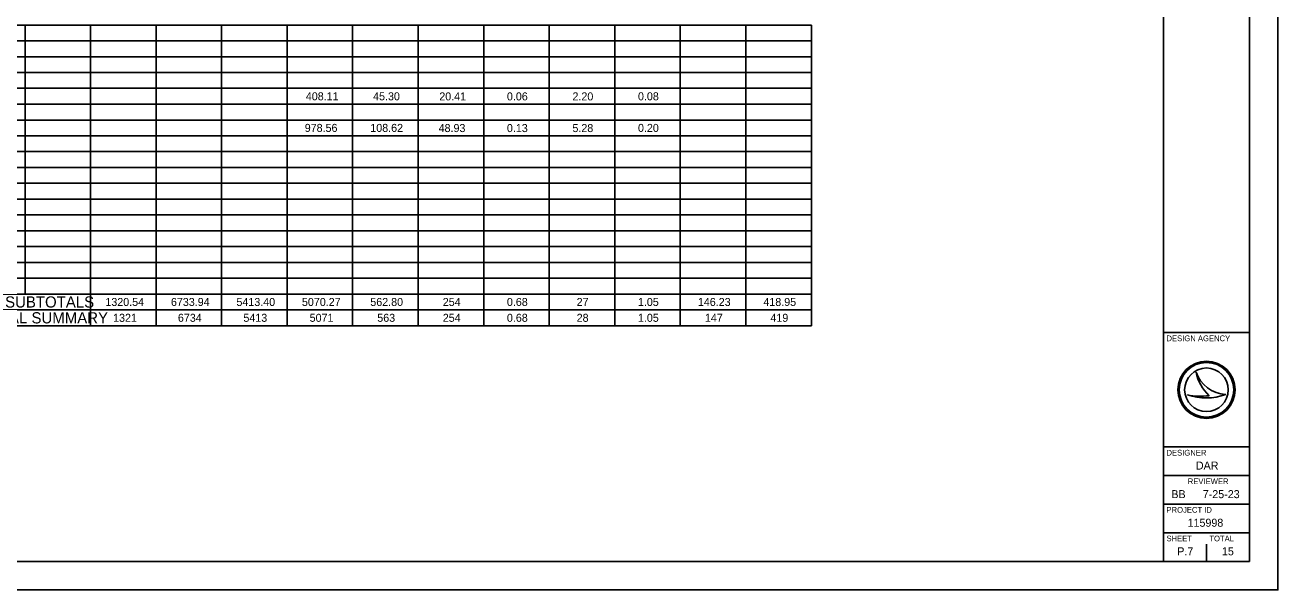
# Model space of a CAD drawing. Extents: x 0 to 34, y 0 to 22.
# Drawn here: x 12.08 to 34, y 0 to 9.88 of the extents above; entities that cross this region are included whole.
import ezdxf

# ---------------------------------------------------------------- set-up
doc = ezdxf.new("R2010")
doc.units = 0
for name, color, linetype in [('Default', 7, 'Continuous'), ('SH_Border', 7, 'Continuous'), ('SH_Cut_Line', 7, 'Continuous'), ('SH_Data', 7, 'Continuous')]:
    doc.layers.add(name, color=color, linetype=linetype)

msp = doc.modelspace()

# ---------------------------------------------------------------- linework, layer by layer
at = {"layer": 'Default'}
for p, q in [((8.642, 9.878), (12.081, 9.878)), ((12.081, 9.878), (13.227, 9.878)), ((12.081, 9.878), (12.081, 9.602)), ((13.227, 9.878), (14.373, 9.878)), ((13.227, 9.878), (13.227, 9.602)), ((14.373, 9.878), (15.52, 9.878)), ((14.373, 9.878), (14.373, 9.602)), ((15.52, 9.878), (25.837, 9.878)), ((15.52, 9.878), (15.52, 9.602)), ((16.666, 9.878), (16.666, 9.602)), ((17.812, 9.878), (17.812, 9.602)), ((18.959, 9.878), (18.959, 9.602)), ((20.105, 9.878), (20.105, 9.602)), ((21.252, 9.878), (21.252, 9.602)), ((22.398, 9.878), (22.398, 9.602)), ((23.544, 9.878), (23.544, 9.602)), ((24.691, 9.878), (24.691, 9.602)), ((25.837, 9.878), (25.837, 9.602)), ((8.642, 9.602), (12.081, 9.602)), ((12.081, 9.602), (13.227, 9.602)), ((12.081, 9.602), (12.081, 9.325)), ((13.227, 9.602), (14.373, 9.602)), ((13.227, 9.602), (13.227, 9.325)), ((14.373, 9.602), (15.52, 9.602)), ((14.373, 9.602), (14.373, 9.325)), ((15.52, 9.602), (25.837, 9.602)), ((15.52, 9.602), (15.52, 9.325)), ((16.666, 9.602), (16.666, 9.325)), ((17.812, 9.602), (17.812, 9.325)), ((18.959, 9.602), (18.959, 9.325)), ((20.105, 9.602), (20.105, 9.325)), ((21.252, 9.602), (21.252, 9.325)), ((22.398, 9.602), (22.398, 9.325)), ((23.544, 9.602), (23.544, 9.325)), ((24.691, 9.602), (24.691, 9.325)), ((25.837, 9.602), (25.837, 9.325)), ((8.642, 9.325), (12.081, 9.325)), ((12.081, 9.325), (13.227, 9.325)), ((12.081, 9.325), (12.081, 9.048)), ((13.227, 9.325), (14.373, 9.325)), ((13.227, 9.325), (13.227, 9.048)), ((14.373, 9.325), (15.52, 9.325)), ((14.373, 9.325), (14.373, 9.048)), ((15.52, 9.325), (25.837, 9.325)), ((15.52, 9.325), (15.52, 9.048)), ((16.666, 9.325), (16.666, 9.048)), ((17.812, 9.325), (17.812, 9.048)), ((18.959, 9.325), (18.959, 9.048)), ((20.105, 9.325), (20.105, 9.048)), ((21.252, 9.325), (21.252, 9.048)), ((22.398, 9.325), (22.398, 9.048)), ((23.544, 9.325), (23.544, 9.048)), ((24.691, 9.325), (24.691, 9.048)), ((25.837, 9.325), (25.837, 9.048)), ((8.642, 9.048), (12.081, 9.048)), ((12.081, 9.048), (13.227, 9.048)), ((12.081, 9.048), (12.081, 8.772)), ((13.227, 9.048), (14.373, 9.048)), ((13.227, 9.048), (13.227, 8.772)), ((14.373, 9.048), (15.52, 9.048)), ((14.373, 9.048), (14.373, 8.772)), ((15.52, 9.048), (25.837, 9.048)), ((15.52, 9.048), (15.52, 8.772)), ((16.666, 9.048), (16.666, 8.772)), ((17.812, 9.048), (17.812, 8.772)), ((18.959, 9.048), (18.959, 8.772)), ((20.105, 9.048), (20.105, 8.772)), ((21.252, 9.048), (21.252, 8.772)), ((22.398, 9.048), (22.398, 8.772)), ((23.544, 9.048), (23.544, 8.772)), ((24.691, 9.048), (24.691, 8.772)), ((25.837, 9.048), (25.837, 8.772)), ((8.642, 8.772), (12.081, 8.772)), ((12.081, 8.772), (13.227, 8.772)), ((12.081, 8.772), (12.081, 8.495)), ((13.227, 8.772), (14.373, 8.772)), ((13.227, 8.772), (13.227, 8.495)), ((14.373, 8.772), (15.52, 8.772)), ((14.373, 8.772), (14.373, 8.495)), ((15.52, 8.772), (25.837, 8.772)), ((15.52, 8.772), (15.52, 8.495)), ((16.666, 8.772), (16.666, 8.495)), ((17.812, 8.772), (17.812, 8.495)), ((18.959, 8.772), (18.959, 8.495)), ((20.105, 8.772), (20.105, 8.495)), ((21.252, 8.772), (21.252, 8.495)), ((22.398, 8.772), (22.398, 8.495)), ((23.544, 8.772), (23.544, 8.495)), ((24.691, 8.772), (24.691, 8.495)), ((25.837, 8.772), (25.837, 8.495)), ((8.642, 8.495), (12.081, 8.495)), ((12.081, 8.495), (13.227, 8.495)), ((12.081, 8.495), (12.081, 8.218)), ((13.227, 8.495), (14.373, 8.495)), ((13.227, 8.495), (13.227, 8.218)), ((14.373, 8.495), (15.52, 8.495)), ((14.373, 8.495), (14.373, 8.218)), ((15.52, 8.495), (25.837, 8.495)), ((15.52, 8.495), (15.52, 8.218)), ((16.666, 8.495), (16.666, 8.218)), ((17.812, 8.495), (17.812, 8.218)), ((18.959, 8.495), (18.959, 8.218)), ((20.105, 8.495), (20.105, 8.218)), ((21.252, 8.495), (21.252, 8.218)), ((22.398, 8.495), (22.398, 8.218)), ((23.544, 8.495), (23.544, 8.218)), ((24.691, 8.495), (24.691, 8.218)), ((25.837, 8.495), (25.837, 8.218)), ((8.642, 8.218), (12.081, 8.218)), ((12.081, 8.218), (13.227, 8.218)), ((12.081, 8.218), (12.081, 7.941)), ((13.227, 8.218), (14.373, 8.218)), ((13.227, 8.218), (13.227, 7.941)), ((14.373, 8.218), (15.52, 8.218)), ((14.373, 8.218), (14.373, 7.941)), ((15.52, 8.218), (25.837, 8.218)), ((15.52, 8.218), (15.52, 7.941)), ((16.666, 8.218), (16.666, 7.941)), ((17.812, 8.218), (17.812, 7.941)), ((18.959, 8.218), (18.959, 7.941)), ((20.105, 8.218), (20.105, 7.941)), ((21.252, 8.218), (21.252, 7.941)), ((22.398, 8.218), (22.398, 7.941)), ((23.544, 8.218), (23.544, 7.941)), ((24.691, 8.218), (24.691, 7.941)), ((25.837, 8.218), (25.837, 7.941)), ((8.642, 7.941), (12.081, 7.941)), ((12.081, 7.941), (13.227, 7.941)), ((12.081, 7.941), (12.081, 7.665)), ((13.227, 7.941), (14.373, 7.941)), ((13.227, 7.941), (13.227, 7.665)), ((14.373, 7.941), (15.52, 7.941)), ((14.373, 7.941), (14.373, 7.665)), ((15.52, 7.941), (25.837, 7.941)), ((15.52, 7.941), (15.52, 7.665)), ((16.666, 7.941), (16.666, 7.665)), ((17.812, 7.941), (17.812, 7.665)), ((18.959, 7.941), (18.959, 7.665)), ((20.105, 7.941), (20.105, 7.665)), ((21.252, 7.941), (21.252, 7.665)), ((22.398, 7.941), (22.398, 7.665)), ((23.544, 7.941), (23.544, 7.665)), ((24.691, 7.941), (24.691, 7.665)), ((25.837, 7.941), (25.837, 7.665)), ((8.642, 7.665), (12.081, 7.665)), ((12.081, 7.665), (13.227, 7.665)), ((12.081, 7.665), (12.081, 7.388)), ((13.227, 7.665), (14.373, 7.665)), ((13.227, 7.665), (13.227, 7.388)), ((14.373, 7.665), (15.52, 7.665)), ((14.373, 7.665), (14.373, 7.388)), ((15.52, 7.665), (25.837, 7.665)), ((15.52, 7.665), (15.52, 7.388)), ((16.666, 7.665), (16.666, 7.388)), ((17.812, 7.665), (17.812, 7.388)), ((18.959, 7.665), (18.959, 7.388)), ((20.105, 7.665), (20.105, 7.388)), ((21.252, 7.665), (21.252, 7.388)), ((22.398, 7.665), (22.398, 7.388)), ((23.544, 7.665), (23.544, 7.388)), ((24.691, 7.665), (24.691, 7.388)), ((25.837, 7.665), (25.837, 7.388)), ((8.642, 7.388), (12.081, 7.388)), ((12.081, 7.388), (13.227, 7.388)), ((12.081, 7.388), (12.081, 7.111)), ((13.227, 7.388), (14.373, 7.388)), ((13.227, 7.388), (13.227, 7.111)), ((14.373, 7.388), (15.52, 7.388)), ((14.373, 7.388), (14.373, 7.111)), ((15.52, 7.388), (25.837, 7.388)), ((15.52, 7.388), (15.52, 7.111)), ((16.666, 7.388), (16.666, 7.111)), ((17.812, 7.388), (17.812, 7.111)), ((18.959, 7.388), (18.959, 7.111)), ((20.105, 7.388), (20.105, 7.111)), ((21.252, 7.388), (21.252, 7.111)), ((22.398, 7.388), (22.398, 7.111)), ((23.544, 7.388), (23.544, 7.111)), ((24.691, 7.388), (24.691, 7.111)), ((25.837, 7.388), (25.837, 7.111)), ((8.642, 7.111), (12.081, 7.111)), ((12.081, 7.111), (13.227, 7.111)), ((12.081, 7.111), (12.081, 6.835)), ((13.227, 7.111), (14.373, 7.111)), ((13.227, 7.111), (13.227, 6.835)), ((14.373, 7.111), (15.52, 7.111)), ((14.373, 7.111), (14.373, 6.835)), ((15.52, 7.111), (25.837, 7.111)), ((15.52, 7.111), (15.52, 6.835)), ((16.666, 7.111), (16.666, 6.835)), ((17.812, 7.111), (17.812, 6.835)), ((18.959, 7.111), (18.959, 6.835)), ((20.105, 7.111), (20.105, 6.835)), ((21.252, 7.111), (21.252, 6.835)), ((22.398, 7.111), (22.398, 6.835)), ((23.544, 7.111), (23.544, 6.835)), ((24.691, 7.111), (24.691, 6.835)), ((25.837, 7.111), (25.837, 6.835)), ((8.642, 6.835), (12.081, 6.835)), ((12.081, 6.835), (13.227, 6.835)), ((12.081, 6.835), (12.081, 6.558)), ((13.227, 6.835), (14.373, 6.835)), ((13.227, 6.835), (13.227, 6.558)), ((14.373, 6.835), (15.52, 6.835)), ((14.373, 6.835), (14.373, 6.558)), ((15.52, 6.835), (25.837, 6.835)), ((15.52, 6.835), (15.52, 6.558)), ((16.666, 6.835), (16.666, 6.558)), ((17.812, 6.835), (17.812, 6.558)), ((18.959, 6.835), (18.959, 6.558)), ((20.105, 6.835), (20.105, 6.558)), ((21.252, 6.835), (21.252, 6.558)), ((22.398, 6.835), (22.398, 6.558)), ((23.544, 6.835), (23.544, 6.558)), ((24.691, 6.835), (24.691, 6.558)), ((25.837, 6.835), (25.837, 6.558)), ((8.642, 6.558), (12.081, 6.558)), ((12.081, 6.558), (13.227, 6.558)), ((12.081, 6.558), (12.081, 6.281)), ((13.227, 6.558), (14.373, 6.558)), ((13.227, 6.558), (13.227, 6.281)), ((14.373, 6.558), (15.52, 6.558)), ((14.373, 6.558), (14.373, 6.281)), ((15.52, 6.558), (25.837, 6.558)), ((15.52, 6.558), (15.52, 6.281)), ((16.666, 6.558), (16.666, 6.281)), ((17.812, 6.558), (17.812, 6.281)), ((18.959, 6.558), (18.959, 6.281)), ((20.105, 6.558), (20.105, 6.281)), ((21.252, 6.558), (21.252, 6.281)), ((22.398, 6.558), (22.398, 6.281)), ((23.544, 6.558), (23.544, 6.281)), ((24.691, 6.558), (24.691, 6.281)), ((25.837, 6.558), (25.837, 6.281)), ((8.642, 6.281), (12.081, 6.281)), ((12.081, 6.281), (13.227, 6.281)), ((12.081, 6.281), (12.081, 6.004)), ((13.227, 6.281), (14.373, 6.281)), ((13.227, 6.281), (13.227, 6.004)), ((14.373, 6.281), (15.52, 6.281)), ((14.373, 6.281), (14.373, 6.004)), ((15.52, 6.281), (25.837, 6.281)), ((15.52, 6.281), (15.52, 6.004)), ((16.666, 6.281), (16.666, 6.004)), ((17.812, 6.281), (17.812, 6.004)), ((18.959, 6.281), (18.959, 6.004)), ((20.105, 6.281), (20.105, 6.004)), ((21.252, 6.281), (21.252, 6.004)), ((22.398, 6.281), (22.398, 6.004)), ((23.544, 6.281), (23.544, 6.004)), ((24.691, 6.281), (24.691, 6.004)), ((25.837, 6.281), (25.837, 6.004)), ((8.642, 6.004), (12.081, 6.004)), ((12.081, 6.004), (13.227, 6.004)), ((12.081, 6.004), (12.081, 5.728)), ((13.227, 6.004), (14.373, 6.004)), ((13.227, 6.004), (13.227, 5.728)), ((14.373, 6.004), (15.52, 6.004)), ((14.373, 6.004), (14.373, 5.728)), ((15.52, 6.004), (25.837, 6.004)), ((15.52, 6.004), (15.52, 5.728)), ((16.666, 6.004), (16.666, 5.728)), ((17.812, 6.004), (17.812, 5.728)), ((18.959, 6.004), (18.959, 5.728)), ((20.105, 6.004), (20.105, 5.728)), ((21.252, 6.004), (21.252, 5.728)), ((22.398, 6.004), (22.398, 5.728)), ((23.544, 6.004), (23.544, 5.728)), ((24.691, 6.004), (24.691, 5.728)), ((25.837, 6.004), (25.837, 5.728)), ((8.642, 5.728), (12.081, 5.728)), ((12.081, 5.728), (13.227, 5.728)), ((12.081, 5.728), (12.081, 5.174)), ((13.227, 5.728), (14.373, 5.728)), ((13.227, 5.728), (13.227, 5.174)), ((14.373, 5.728), (15.52, 5.728)), ((14.373, 5.728), (14.373, 5.174)), ((15.52, 5.728), (25.837, 5.728)), ((15.52, 5.728), (15.52, 5.174)), ((16.666, 5.728), (16.666, 5.174)), ((17.812, 5.728), (17.812, 5.174)), ((18.959, 5.728), (18.959, 5.174)), ((20.105, 5.728), (20.105, 5.174)), ((21.252, 5.728), (21.252, 5.174)), ((22.398, 5.728), (22.398, 5.174)), ((23.544, 5.728), (23.544, 5.174)), ((24.691, 5.728), (24.691, 5.174)), ((25.837, 5.728), (25.837, 5.174)), ((8.642, 5.451), (12.081, 5.451)), ((12.081, 5.451), (13.227, 5.451)), ((13.227, 5.451), (14.373, 5.451)), ((14.373, 5.451), (15.52, 5.451)), ((15.52, 5.451), (25.837, 5.451)), ((8.642, 5.174), (12.081, 5.174)), ((12.081, 5.174), (13.227, 5.174)), ((13.227, 5.174), (14.373, 5.174)), ((13.227, 5.174), (13.227, 4.898)), ((14.373, 5.174), (15.52, 5.174)), ((14.373, 5.174), (14.373, 4.898)), ((15.52, 5.174), (25.837, 5.174)), ((15.52, 5.174), (15.52, 4.898)), ((16.666, 5.174), (16.666, 4.898)), ((17.812, 5.174), (17.812, 4.898)), ((18.959, 5.174), (18.959, 4.898)), ((20.105, 5.174), (20.105, 4.898)), ((21.252, 5.174), (21.252, 4.898)), ((22.398, 5.174), (22.398, 4.898)), ((23.544, 5.174), (23.544, 4.898)), ((24.691, 5.174), (24.691, 4.898)), ((25.837, 5.174), (25.837, 4.898)), ((8.642, 4.898), (12.081, 4.898)), ((12.081, 4.898), (13.227, 4.898)), ((13.227, 4.898), (14.373, 4.898)), ((13.227, 4.898), (13.227, 4.621)), ((14.373, 4.898), (15.52, 4.898)), ((14.373, 4.898), (14.373, 4.621)), ((15.52, 4.898), (25.837, 4.898)), ((15.52, 4.898), (15.52, 4.621)), ((16.666, 4.898), (16.666, 4.621)), ((17.812, 4.898), (17.812, 4.621)), ((18.959, 4.898), (18.959, 4.621)), ((20.105, 4.898), (20.105, 4.621)), ((21.252, 4.898), (21.252, 4.621)), ((22.398, 4.898), (22.398, 4.621)), ((23.544, 4.898), (23.544, 4.621)), ((24.691, 4.898), (24.691, 4.621)), ((25.837, 4.898), (25.837, 4.621)), ((8.642, 4.621), (12.081, 4.621)), ((12.081, 4.621), (13.227, 4.621)), ((13.227, 4.621), (14.373, 4.621)), ((14.373, 4.621), (15.52, 4.621)), ((15.52, 4.621), (25.837, 4.621))]:
    msp.add_line(p, q, dxfattribs=at)
at = {"layer": 'SH_Border'}
for p, q in [((32, 0.5), (32, 21.5)), ((32, 4.5), (33.5, 4.5)), ((32, 2.5), (33.5, 2.5)), ((32, 2), (33.5, 2)), ((32, 1.5), (33.5, 1.5)), ((32, 1), (33.5, 1))]:
    msp.add_line(p, q, dxfattribs=at)
msp.add_lwpolyline([(1.5, 21.5), (33.5, 21.5), (33.5, 0.5), (1.5, 0.5)], close=True, dxfattribs=at)
at = {"layer": 'SH_Cut_Line'}
msp.add_lwpolyline([(0, 0), (34, 0), (34, 22), (0, 22)], close=True, dxfattribs=at)
at = {"layer": 'SH_Data'}
for p, q in [((32.567, 3.81), (32.567, 3.81)), ((32.417, 3.41), (32.417, 3.41)), ((32.75, 3.5), (32.75, 3.5)), ((33.087, 3.419), (33.087, 3.419)), ((32.375, 0.675), (32.375, 0.675)), ((32.75, 0.5), (32.75, 0.8))]:
    msp.add_line(p, q, dxfattribs=at)
for radius in [0.5, 0.477, 0.477, 0.382]:
    msp.add_circle((32.75, 3.5), radius, dxfattribs=at)
for centre, radius, start, end in [((33.116, 3.998), 0.58, 198.9257, 198.9319), ((33.347, 3.97), 0.796, 191.6379, 191.6421), ((33.116, 3.998), 0.58, 198.9319, 267.1657), ((33.347, 3.97), 0.796, 191.6421, 226.0947), ((32.739, 4.37), 1.013, 251.4576, 290.0832), ((32.648, 4.654), 1.266, 259.4964, 259.4995), ((32.739, 4.37), 1.013, 251.4527, 251.4576), ((32.648, 4.654), 1.266, 259.4995, 276.6672)]:
    msp.add_arc(centre, radius, start, end, dxfattribs=at)

# ---------------------------------------------------------------- texts
at = {"layer": 'Default'}
for s, height, p in [('408.11', 0.14, (16.993, 8.563)), ('45.30', 0.14, (18.17, 8.563)), ('20.41', 0.14, (19.328, 8.561)), ('0.06', 0.14, (20.511, 8.561)), ('2.20', 0.14, (21.658, 8.561)), ('0.08', 0.14, (22.804, 8.563)), ('978.56', 0.14, (16.974, 8.01)), ('108.62', 0.14, (18.121, 8.01)), ('48.93', 0.14, (19.316, 8.007)), ('0.13', 0.14, (20.511, 8.007)), ('5.28', 0.14, (21.657, 8.007)), ('0.20', 0.14, (22.804, 8.01)), ('SUBTOTALS', 0.196, (11.731, 4.938)), ('1320.54', 0.14, (13.486, 4.966)), ('6733.94', 0.14, (14.633, 4.966)), ('5413.40', 0.14, (15.779, 4.966)), ('5070.27', 0.14, (16.925, 4.966)), ('562.80', 0.14, (18.121, 4.966)), ('254', 0.14, (19.389, 4.966)), ('0.68', 0.14, (20.511, 4.966)), ('27', 0.14, (21.731, 4.966)), ('1.05', 0.14, (22.803, 4.966)), ('146.23', 0.14, (23.852, 4.966)), ('418.95', 0.14, (24.998, 4.966)), ('TOTALS CARRIED TO GENERAL SUMMARY', 0.196, (8.086, 4.661)), ('1321', 0.14, (13.621, 4.689)), ('6734', 0.14, (14.755, 4.689)), ('5413', 0.14, (15.901, 4.689)), ('5071', 0.14, (17.06, 4.689)), ('563', 0.14, (18.243, 4.689)), ('254', 0.14, (19.389, 4.689)), ('0.68', 0.14, (20.511, 4.689)), ('28', 0.14, (21.731, 4.689)), ('1.05', 0.14, (22.803, 4.689)), ('147', 0.14, (23.975, 4.689)), ('419', 0.14, (25.121, 4.689))]:
    msp.add_text(s, height=height, dxfattribs=at).set_placement(p)
at = {"layer": 'SH_Data'}
for s, height, p in [('DESIGN AGENCY', 0.1, (32.05, 4.35)), ('DESIGNER', 0.1, (32.05, 2.35)), ('DAR', 0.14, (32.564, 2.105)), ('REVIEWER', 0.1, (32.422, 1.85)), ('BB', 0.14, (32.135, 1.605)), ('7-25-23', 0.14, (32.685, 1.605)), ('PROJECT ID', 0.1, (32.05, 1.35)), ('115998', 0.14, (32.419, 1.105)), ('SHEET', 0.1, (32.05, 0.85)), ('TOTAL', 0.1, (32.8, 0.85)), ('P.7', 0.14, (32.239, 0.605)), ('15', 0.14, (33.02, 0.605))]:
    msp.add_text(s, height=height, dxfattribs=at).set_placement(p)

doc.saveas('drawing.dxf')
